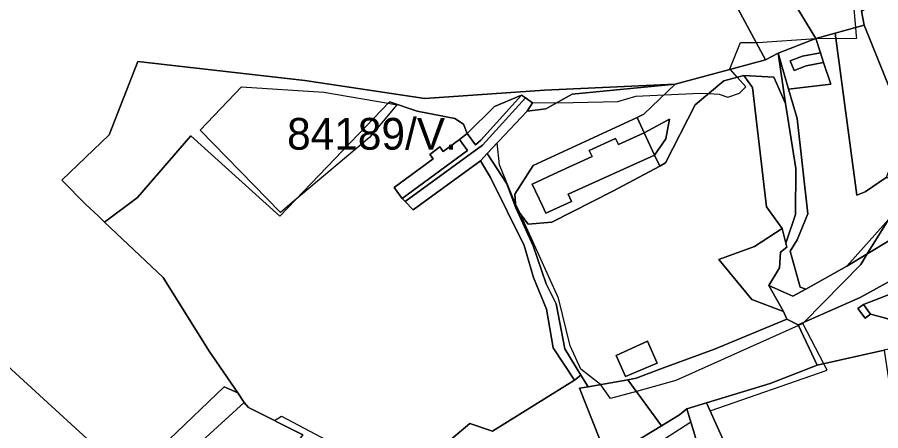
# Model space of a CAD drawing. Extents: x -477304 to -465429, y -1159113 to -1149210.
# Drawn here: x -475692.5 to -475284.1, y -1154186.7 to -1153991.1 of the extents above; entities that cross this region are included whole.
import ezdxf

# ---------------------------------------------------------------- set-up
doc = ezdxf.new("R2010")
doc.units = 0
for name, color, linetype in [('BPEJ_s', 7, 'Continuous'), ('orna_s', 7, 'Continuous'), ('ostatni_s', 7, 'Continuous'), ('PUPFL_s', 7, 'Continuous'), ('trav_porost_s', 7, 'Continuous'), ('zahrada_s', 7, 'Continuous')]:
    doc.layers.add(name, color=color, linetype=linetype)

msp = doc.modelspace()

# ---------------------------------------------------------------- linework, layer by layer
at = {"layer": 'BPEJ_s'}
for points in [[(-475456.83, -1154079.37), (-475457, -1154079), (-475464.5, -1154061), (-475465.48, -1154050.5), (-475470.23, -1154055.58), (-475473.41, -1154058.98), (-475505.22, -1154082.21), (-475509, -1154078.3), (-475510.43, -1154076.82), (-475479.58, -1154054.11), (-475483.41, -1154048.92), (-475479.68, -1154046.08), (-475475.76, -1154051.42), (-475473.25, -1154049.3), (-475454.02, -1154027.94), (-475452.19, -1154029.22), (-475448.86, -1154031.54), (-475429.5, -1154031.5), (-475408.5, -1154031), (-475400, -1154028.5), (-475386.61, -1154027.84), (-475369.5, -1154027), (-475365.55, -1154027.22), (-475360.5, -1154027.5), (-475356.5, -1154029), (-475351, -1154027), (-475348, -1154024), (-475352, -1154019.47), (-475355.24, -1154015.8), (-475355.5, -1154015.5), (-475350.5, -1154003), (-475343.12, -1154003), (-475342.5, -1154003), (-475314.88, -1154001.19), (-475295.5, -1154001), (-475295.59, -1154000), (-475295.95, -1153995.97), (-475298, -1153973)], [(-475470.23, -1154055.58), (-475473.41, -1154058.98), (-475505.22, -1154082.21), (-475509, -1154078.3), (-475510.43, -1154076.82), (-475479.58, -1154054.11), (-475483.41, -1154048.92), (-475479.68, -1154046.08), (-475475.76, -1154051.42), (-475473.25, -1154049.3), (-475454.02, -1154027.94), (-475452.19, -1154029.22), (-475448.86, -1154031.54), (-475429.5, -1154031.5), (-475408.5, -1154031), (-475400, -1154028.5), (-475386.61, -1154027.84), (-475369.5, -1154027), (-475365.55, -1154027.22), (-475360.5, -1154027.5), (-475356.5, -1154029), (-475351, -1154027), (-475348, -1154024), (-475352, -1154019.47), (-475355.24, -1154015.8), (-475355.5, -1154015.5), (-475350.5, -1154003), (-475343.12, -1154003), (-475342.5, -1154003), (-475314.88, -1154001.19), (-475295.5, -1154001), (-475295.59, -1154000), (-475295.95, -1153995.97), (-475298, -1153973)], [(-475586.5, -1154024), (-475547.5, -1154026.5), (-475517.05, -1154031.78), (-475513, -1154032.48), (-475526, -1154048), (-475561.51, -1154078.01), (-475568, -1154083.5), (-475606, -1154044.5), (-475586.5, -1154024)], [(-475389.5, -1154192.5), (-475373.93, -1154182.46), (-475375.79, -1154176.29), (-475366.47, -1154173.48), (-475364.79, -1154177.23), (-475309.5, -1154158), (-475311.05, -1154155.04), (-475321, -1154136), (-475323.02, -1154136.91), (-475381, -1154163), (-475399.68, -1154168.12), (-475412, -1154171.5), (-475416.5, -1154165), (-475416.69, -1154164.85), (-475426, -1154157.5), (-475431, -1154146.5), (-475436.5, -1154124), (-475454.89, -1154083.63), (-475456.83, -1154079.37), (-475457, -1154079), (-475464.5, -1154061), (-475465.48, -1154050.5), (-475470.23, -1154055.58)], [(-475280.64, -1154087.06), (-475290.48, -1154103.08), (-475293.5, -1154108), (-475320.41, -1154135.4), (-475321, -1154136), (-475323.02, -1154136.91), (-475381, -1154163), (-475399.68, -1154168.12), (-475412, -1154171.5), (-475416.5, -1154165), (-475416.69, -1154164.85), (-475426, -1154157.5), (-475431, -1154146.5), (-475436.5, -1154124), (-475454.89, -1154083.63), (-475456.83, -1154079.37)], [(-475276.5, -1154232), (-475322, -1154224.5), (-475339.3, -1154220.45), (-475345.5, -1154219), (-475346.33, -1154218.58), (-475356.96, -1154213.17), (-475366.04, -1154208.56), (-475376, -1154203.5), (-475389.5, -1154192.5), (-475373.93, -1154182.46), (-475375.79, -1154176.29), (-475366.47, -1154173.48), (-475364.79, -1154177.23), (-475309.5, -1154158), (-475311.05, -1154155.04), (-475321, -1154136), (-475320.41, -1154135.4), (-475293.5, -1154108), (-475290.48, -1154103.08), (-475280.64, -1154087.06)], [(-475613.99, -1154199.7), (-475585.15, -1154173.3), (-475583.1, -1154175.64), (-475570.82, -1154181.91), (-475567.62, -1154179.77), (-475527.61, -1154200.97)], [(-475613.99, -1154199.7), (-475585.15, -1154173.3), (-475583.1, -1154175.64), (-475570.82, -1154181.91), (-475567.62, -1154179.77), (-475527.61, -1154200.97)]]:
    msp.add_lwpolyline(points, dxfattribs=at)
msp.add_lwpolyline([(-475561.51, -1154078.01), (-475568, -1154083.5), (-475606, -1154044.5), (-475586.5, -1154024), (-475547.5, -1154026.5), (-475517.05, -1154031.78), (-475513, -1154032.48), (-475526, -1154048)], close=True, dxfattribs=at)
at = {"layer": 'orna_s'}
msp.add_lwpolyline([(-475365.71, -1154209.66), (-475375.79, -1154176.29), (-475366.47, -1154173.48), (-475346.87, -1154217.23)], close=True, dxfattribs=at)
at = {"layer": 'ostatni_s'}
for points in [[(-475277.72, -1154027.2), (-475271.83, -1154042.77), (-475281.56, -1154066.98), (-475291.57, -1154073.68), (-475295.52, -1154075.22), (-475305.75, -1153998.67), (-475291.99, -1153994.88), (-475278.7, -1154027.66)], [(-475311.14, -1154012.48), (-475312.66, -1154007.91), (-475314.88, -1154001.19), (-475305.75, -1153998.67), (-475295.52, -1154075.22), (-475291.57, -1154073.68), (-475281.56, -1154066.98), (-475271.49, -1154066.91), (-475271.41, -1154072.31), (-475278.98, -1154085.2), (-475300.17, -1154108.93), (-475319.6, -1154119.7), (-475322.19, -1154118.77), (-475326.98, -1154101.79), (-475323.63, -1154096.48), (-475318.62, -1154084.07), (-475323.67, -1154039.05), (-475327.77, -1154025.17), (-475307.73, -1154022.79)], [(-475395.97, -1154045.86), (-475399.41, -1154038.47), (-475396.2, -1154036.98), (-475381.35, -1154022.83), (-475352.09, -1154014.95), (-475338.69, -1154011.34), (-475332.62, -1154008.15), (-475329.16, -1154031.92), (-475334.71, -1154019.5), (-475348.86, -1154018.62), (-475358.33, -1154021.18), (-475371.85, -1154032.49), (-475385.88, -1154060.01), (-475388.68, -1154061.5), (-475391.09, -1154056.33), (-475385.76, -1154048.71), (-475384.07, -1154039.31)], [(-475324.47, -1154084.47), (-475324.24, -1154062.71), (-475329.16, -1154031.92), (-475332.62, -1154008.15), (-475327.77, -1154025.17), (-475323.67, -1154039.05), (-475318.62, -1154084.07), (-475323.63, -1154096.48), (-475326.98, -1154101.79), (-475322.19, -1154118.77), (-475319.6, -1154119.7), (-475325.76, -1154123.12), (-475337.08, -1154117.98), (-475332.03, -1154109.71), (-475331.51, -1154102.22), (-475328.55, -1154099.87), (-475329.03, -1154097.97)], [(-475319.4, -1154014.09), (-475325.12, -1154016.33), (-475326.9, -1154011.81), (-475321.18, -1154009.57), (-475312.66, -1154007.91), (-475311.14, -1154012.48)], [(-475443.17, -1154025.66), (-475381.35, -1154022.83), (-475430, -1154027.52), (-475442.59, -1154034.47), (-475451.43, -1154035.5), (-475448.86, -1154031.54), (-475452.19, -1154029.22), (-475454.02, -1154027.94), (-475466.76, -1154033.41), (-475479.68, -1154046.08), (-475481.48, -1154041.71), (-475485.55, -1154038.97), (-475503.43, -1154035.56), (-475516.49, -1154031.19), (-475568.39, -1154085.17), (-475610.44, -1154047.21), (-475635.71, -1154076.42), (-475651.23, -1154087.99), (-475654.25, -1154085.13), (-475660.13, -1154079.7), (-475671.45, -1154068.19), (-475649.02, -1154046.75), (-475635.42, -1154012.08), (-475556.44, -1154021.02), (-475499.82, -1154029.51)], [(-475385.88, -1154060.01), (-475371.85, -1154032.49), (-475358.33, -1154021.18), (-475348.86, -1154018.62), (-475344.72, -1154024.42), (-475338.14, -1154080.72), (-475330.81, -1154090.98), (-475343.85, -1154099.51), (-475360.69, -1154105.77), (-475345.06, -1154124.7), (-475330.19, -1154130.33), (-475328.53, -1154133.94), (-475362.74, -1154148.1), (-475386.87, -1154156.88), (-475399.81, -1154161.88), (-475403.72, -1154162.57), (-475422.46, -1154165.86), (-475426.04, -1154160.45), (-475433.47, -1154147.9), (-475437.69, -1154126.61), (-475442.38, -1154117.15), (-475448.49, -1154099.2), (-475456.66, -1154081.31), (-475450.86, -1154088.92), (-475439.73, -1154088.08), (-475410.9, -1154073.37), (-475388.68, -1154061.5)], [(-475338.14, -1154080.72), (-475344.72, -1154024.42), (-475348.86, -1154018.62), (-475334.71, -1154019.5), (-475329.16, -1154031.92), (-475324.24, -1154062.71), (-475324.47, -1154084.47), (-475329.03, -1154097.97), (-475330.81, -1154090.98)], [(-475271.83, -1154042.77), (-475277.72, -1154027.2), (-475263.79, -1154020.57), (-475259.89, -1154027.21), (-475261.41, -1154043.8), (-475255.76, -1154062.26), (-475260.41, -1154084.94), (-475300.17, -1154108.93), (-475278.98, -1154085.2), (-475271.41, -1154072.31), (-475271.49, -1154066.91)], [(-475448.46, -1154061.24), (-475457.24, -1154074.81), (-475456.66, -1154081.31), (-475461.12, -1154069.65), (-475470.23, -1154055.58), (-475451.43, -1154035.5), (-475442.59, -1154034.47), (-475430, -1154027.52), (-475381.35, -1154022.83), (-475396.2, -1154036.98), (-475399.41, -1154038.47)], [(-475454.02, -1154027.94), (-475473.25, -1154049.3), (-475475.76, -1154051.42), (-475479.68, -1154046.08), (-475466.76, -1154033.41)], [(-475391.09, -1154056.33), (-475388.68, -1154061.5), (-475410.9, -1154073.37), (-475439.73, -1154088.08), (-475450.86, -1154088.92), (-475456.66, -1154081.31), (-475457.24, -1154074.81), (-475448.46, -1154061.24), (-475399.41, -1154038.47), (-475395.97, -1154045.86), (-475408.15, -1154051.38), (-475409.51, -1154048.47), (-475422.01, -1154054.14), (-475420.65, -1154057.05), (-475436.86, -1154064.4), (-475448.98, -1154070.03), (-475444.17, -1154080.39), (-475442.56, -1154083.86), (-475430.44, -1154078.23), (-475432, -1154074.87)], [(-475391.09, -1154056.33), (-475432, -1154074.87), (-475430.44, -1154078.23), (-475442.56, -1154083.86), (-475444.17, -1154080.39), (-475448.98, -1154070.03), (-475436.86, -1154064.4), (-475420.65, -1154057.05), (-475422.01, -1154054.14), (-475409.51, -1154048.47), (-475408.15, -1154051.38), (-475395.97, -1154045.86)], [(-475479.58, -1154054.11), (-475510.43, -1154076.82), (-475514.26, -1154071.63), (-475495.84, -1154058.07), (-475497.4, -1154055.97), (-475492.68, -1154052.49), (-475491.12, -1154054.6), (-475483.41, -1154048.92)], [(-475429, -1154162.83), (-475439.13, -1154147.48), (-475442.19, -1154129.21), (-475448.3, -1154114.28), (-475452.77, -1154099.1), (-475468.73, -1154066.87), (-475473.41, -1154058.98), (-475470.23, -1154055.58), (-475461.12, -1154069.65), (-475456.66, -1154081.31), (-475448.49, -1154099.2), (-475442.38, -1154117.15), (-475437.69, -1154126.61), (-475433.47, -1154147.9), (-475426.04, -1154160.45)], [(-475262.28, -1154101.62), (-475273.91, -1154112.63), (-475293.92, -1154123.61), (-475323.15, -1154136.62), (-475328.53, -1154133.94), (-475330.19, -1154130.33), (-475337.08, -1154117.98), (-475325.76, -1154123.12), (-475319.6, -1154119.7), (-475300.17, -1154108.93), (-475260.41, -1154084.94), (-475239.39, -1154066.92), (-475237.48, -1154072.85)], [(-475360.69, -1154105.77), (-475343.85, -1154099.51), (-475330.81, -1154090.98), (-475329.03, -1154097.97), (-475328.55, -1154099.87), (-475331.51, -1154102.22), (-475332.03, -1154109.71), (-475337.08, -1154117.98), (-475330.19, -1154130.33), (-475345.06, -1154124.7)], [(-475292.33, -1154126.96), (-475294.93, -1154128.89), (-475291.49, -1154133.53), (-475288.93, -1154131.54), (-475280.6, -1154133.78), (-475277.07, -1154142.19), (-475275.1, -1154146.89), (-475282.46, -1154148.53), (-475314.23, -1154155.76), (-475323.15, -1154136.62), (-475293.92, -1154123.61), (-475273.91, -1154112.63), (-475262.28, -1154101.62), (-475266.39, -1154108.37), (-475267.78, -1154109.82), (-475271.73, -1154113.93), (-475274.08, -1154119.9)], [(-475263.81, -1154113.62), (-475256.09, -1154121.04), (-475260.04, -1154125.15), (-475268.34, -1154128.63), (-475264.81, -1154137.04), (-475268.58, -1154138.62), (-475268.46, -1154138.9), (-475273.03, -1154140.82), (-475273.15, -1154140.54), (-475277.07, -1154142.19), (-475280.6, -1154133.78), (-475288.93, -1154131.54), (-475292.33, -1154126.96), (-475274.08, -1154119.9), (-475271.73, -1154113.93), (-475267.78, -1154109.82), (-475266.39, -1154108.37), (-475263.08, -1154111.56)], [(-475294.93, -1154128.89), (-475292.33, -1154126.96), (-475288.93, -1154131.54), (-475291.49, -1154133.53)], [(-475394.46, -1154144.33), (-475389.94, -1154154.67), (-475404.82, -1154161.05), (-475409.27, -1154151.06)], [(-475404.82, -1154161.05), (-475389.94, -1154154.67), (-475394.46, -1154144.33), (-475409.27, -1154151.06)], [(-475267.07, -1154235.42), (-475275.71, -1154237.64), (-475298.8, -1154237.69), (-475346.87, -1154217.23), (-475366.47, -1154173.48), (-475336.47, -1154164.38), (-475314.23, -1154155.76), (-475282.46, -1154148.53), (-475277.94, -1154179.1)]]:
    msp.add_lwpolyline(points, close=True, dxfattribs=at)
msp.add_lwpolyline([(-475557.51, -1154188.7), (-475583.1, -1154175.64), (-475585.15, -1154173.3), (-475588.2, -1154168.75), (-475601.71, -1154149.02), (-475623.48, -1154114.25), (-475651.23, -1154087.99), (-475635.71, -1154076.42), (-475610.44, -1154047.21), (-475568.39, -1154085.17), (-475516.49, -1154031.19), (-475503.43, -1154035.56), (-475485.55, -1154038.97), (-475481.48, -1154041.71), (-475479.68, -1154046.08), (-475483.41, -1154048.92), (-475491.12, -1154054.6), (-475492.68, -1154052.49), (-475497.4, -1154055.97), (-475495.84, -1154058.07), (-475514.26, -1154071.63), (-475510.43, -1154076.82), (-475509, -1154078.3), (-475505.22, -1154082.21), (-475473.41, -1154058.98), (-475468.73, -1154066.87), (-475452.77, -1154099.1), (-475448.3, -1154114.28), (-475442.19, -1154129.21), (-475439.13, -1154147.48), (-475429, -1154162.83), (-475467.72, -1154186.86), (-475478.48, -1154183.29), (-475512.65, -1154212.2)], dxfattribs=at)
at = {"layer": 'PUPFL_s'}
for points in [[(-475305.75, -1153998.67), (-475314.88, -1154001.19), (-475332.9, -1153971.29), (-475318.22, -1153960.33), (-475311.89, -1153960.94), (-475306.7, -1153962.3), (-475300.88, -1153965.61), (-475296.72, -1153971.06), (-475295.61, -1153976.48), (-475293.29, -1153988.27), (-475291.99, -1153994.88)], [(-475314.88, -1154001.19), (-475332.62, -1154008.15), (-475338.69, -1154011.34), (-475352.75, -1153984.87), (-475344.99, -1153979.39), (-475332.9, -1153971.29)], [(-475323.15, -1154136.62), (-475314.23, -1154155.76), (-475336.47, -1154164.38), (-475366.47, -1154173.48), (-475375.79, -1154176.29), (-475379.32, -1154179.16), (-475387.85, -1154184.37), (-475403.72, -1154162.57), (-475399.81, -1154161.88), (-475386.87, -1154156.88), (-475362.74, -1154148.1), (-475328.53, -1154133.94)], [(-475473.22, -1154236.05), (-475481.23, -1154228.2), (-475505.35, -1154213.34), (-475507.98, -1154215.32), (-475512.65, -1154212.2), (-475478.48, -1154183.29), (-475467.72, -1154186.86), (-475429, -1154162.83), (-475426.04, -1154160.45), (-475422.46, -1154165.86), (-475426.6, -1154166.59), (-475414.25, -1154197.63), (-475438.58, -1154204.34), (-475454.72, -1154212.8), (-475465.22, -1154223.55)], [(-475404.7, -1154194.66), (-475414.25, -1154197.63), (-475426.6, -1154166.59), (-475422.46, -1154165.86), (-475403.72, -1154162.57), (-475387.85, -1154184.37)], [(-475365.71, -1154209.66), (-475383.75, -1154202.61), (-475391.07, -1154198.89), (-475404.7, -1154194.66), (-475387.85, -1154184.37), (-475379.32, -1154179.16), (-475375.79, -1154176.29)]]:
    msp.add_lwpolyline(points, close=True, dxfattribs=at)
for points in [[(-475352.75, -1153984.87), (-475338.69, -1154011.34), (-475352.09, -1154014.95), (-475381.35, -1154022.83), (-475443.17, -1154025.66), (-475499.82, -1154029.51), (-475556.44, -1154021.02), (-475635.42, -1154012.08), (-475649.02, -1154046.75), (-475671.45, -1154068.19), (-475660.13, -1154079.7), (-475654.25, -1154085.13), (-475651.23, -1154087.99), (-475623.48, -1154114.25), (-475601.71, -1154149.02), (-475588.2, -1154168.75), (-475594.61, -1154165.94), (-475620.6, -1154190.85), (-475642.43, -1154206.13), (-475806.71, -1154055.75), (-475825.65, -1154044.41), (-475814.03, -1153985.87)], [(-475814.03, -1153985.87), (-475825.65, -1154044.41), (-475806.71, -1154055.75), (-475642.43, -1154206.13), (-475620.6, -1154190.85), (-475594.61, -1154165.94), (-475588.2, -1154168.75), (-475585.15, -1154173.3), (-475613.99, -1154199.7), (-475637.63, -1154216.91), (-475632.72, -1154228.55), (-475614.41, -1154259.01), (-475610.06, -1154266.26), (-475615.38, -1154280.61)]]:
    msp.add_lwpolyline(points, dxfattribs=at)
at = {"layer": 'trav_porost_s'}
for points in [[(-475332.62, -1154008.15), (-475314.88, -1154001.19), (-475312.66, -1154007.91), (-475321.18, -1154009.57), (-475326.9, -1154011.81), (-475325.12, -1154016.33), (-475319.4, -1154014.09), (-475311.14, -1154012.48), (-475307.73, -1154022.79), (-475327.77, -1154025.17)], [(-475637.63, -1154216.91), (-475613.99, -1154199.7), (-475585.15, -1154173.3), (-475583.1, -1154175.64), (-475557.51, -1154188.7), (-475614.41, -1154259.01), (-475632.72, -1154228.55)]]:
    msp.add_lwpolyline(points, close=True, dxfattribs=at)
at = {"layer": 'zahrada_s'}
for points in [[(-475250.88, -1153961.16), (-475243.2, -1153970.22), (-475238.88, -1153980.35), (-475235.95, -1153991.93), (-475238.13, -1154008.37), (-475239.18, -1154008.87), (-475263.79, -1154020.57), (-475277.72, -1154027.2), (-475278.7, -1154027.66), (-475291.99, -1153994.88), (-475293.29, -1153988.27), (-475279.95, -1153980.18)], [(-475452.19, -1154029.22), (-475472.47, -1154051.69), (-475509, -1154078.3), (-475510.43, -1154076.82), (-475479.58, -1154054.11), (-475483.41, -1154048.92), (-475479.68, -1154046.08), (-475475.76, -1154051.42), (-475473.25, -1154049.3), (-475454.02, -1154027.94)], [(-475472.47, -1154051.69), (-475452.19, -1154029.22), (-475448.86, -1154031.54), (-475451.43, -1154035.5), (-475470.23, -1154055.58), (-475473.41, -1154058.98), (-475505.22, -1154082.21), (-475509, -1154078.3)], [(-475385.76, -1154048.71), (-475391.09, -1154056.33), (-475395.97, -1154045.86), (-475384.07, -1154039.31)]]:
    msp.add_lwpolyline(points, close=True, dxfattribs=at)

# ---------------------------------------------------------------- texts
at = {"layer": 'BPEJ_s'}
msp.add_text('84189/V.', height=15, dxfattribs=at).set_placement((-475564.9, -1154053.75))

doc.saveas('drawing.dxf')
